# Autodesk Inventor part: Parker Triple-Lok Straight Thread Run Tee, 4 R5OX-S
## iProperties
Shininess: 64.0
Length Units: 11272
Angle Units: 11279
Time Units: 11290
Mass Units: 11286
Length Display Precision: 3
Angle Display Precision: 2
Created: 2001-12
Part Number: Parker Triple-Lok Straight Thread Run Tee, 4 R5OX-S
Description: Parker Triple-Lok Straight Thread Run Tee, 4 R5OX-S
Document SubType Name: Modeling
Designer: Administrator
Density: 0.0
Volumn: 0.0
Area: 0.0
PropertySet Name: Model Information
Control State: 0
Master: False
Checked Out: False
Last Check In By: Charles Bliss
Last Check In Date: 2003-09-27
Author: Administrator
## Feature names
1. Extrusion1
2. Extrusion2
3. Revolution2
4. Circular Pattern1
5. Fillet1
6. Revolution3
7. Extrusion3
8. Revolution4
9. Mirror4
10. Extrusion4
11. Extrusion5
12. Chamfer1
13. Hole1
14. Hole2
15. Revolution8
